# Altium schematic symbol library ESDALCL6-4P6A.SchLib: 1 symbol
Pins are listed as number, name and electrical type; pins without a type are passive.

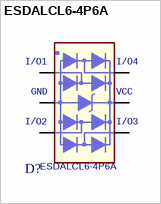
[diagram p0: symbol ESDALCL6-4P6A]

## ESDALCL6-4P6A
designator D?
footprint ST_SOT666
pins: 1 I/O1, 2 GND, 3 I/O2, 4 I/O3, 5 VCC, 6 I/O4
